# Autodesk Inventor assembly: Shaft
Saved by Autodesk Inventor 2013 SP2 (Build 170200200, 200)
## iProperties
Created: 2020-02
Part Number: Shaft
Document SubType Name: Assembly
Designer: DELL
ClientObjectVersion: 1
Author: DELL
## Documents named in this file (2)
- C:\Users\DELL\Dropbox\Inventor\Projects\Quadcopter F450\Assemblies\Servo - Design Accelerator Spline Tutorial\Design Accelerator - 5mm Shaft and Spline\Design Accelerator\Shaft1.iam
- C:\Users\DELL\Dropbox\Inventor\Projects\Quadcopter F450\Assemblies\Servo - Design Accelerator Spline Tutorial\Design Accelerator - 5mm Shaft and Spline\Design Accelerator\Shaft1.ipt
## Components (1 placed, 1 different names)
1. Shaft:1
